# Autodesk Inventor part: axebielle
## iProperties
Shininess: 21.0
Length Units: 11269
Angle Units: 11279
Time Units: 11290
Mass Units: 11283
Length Display Precision: 3
Angle Display Precision: 2
Compacted: True
Created: 2001-12
Part Number: axebielle
Material: Par défaut
Document SubType Name: Modélisation
Designer: pichon
Density: 0.0
Volumn: 0.0
Area: 0.0
PropertySet Name: Model Information
Control State: 0
Master: False
Checked Out: False
Author: pichon
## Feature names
1. Extrusion1
